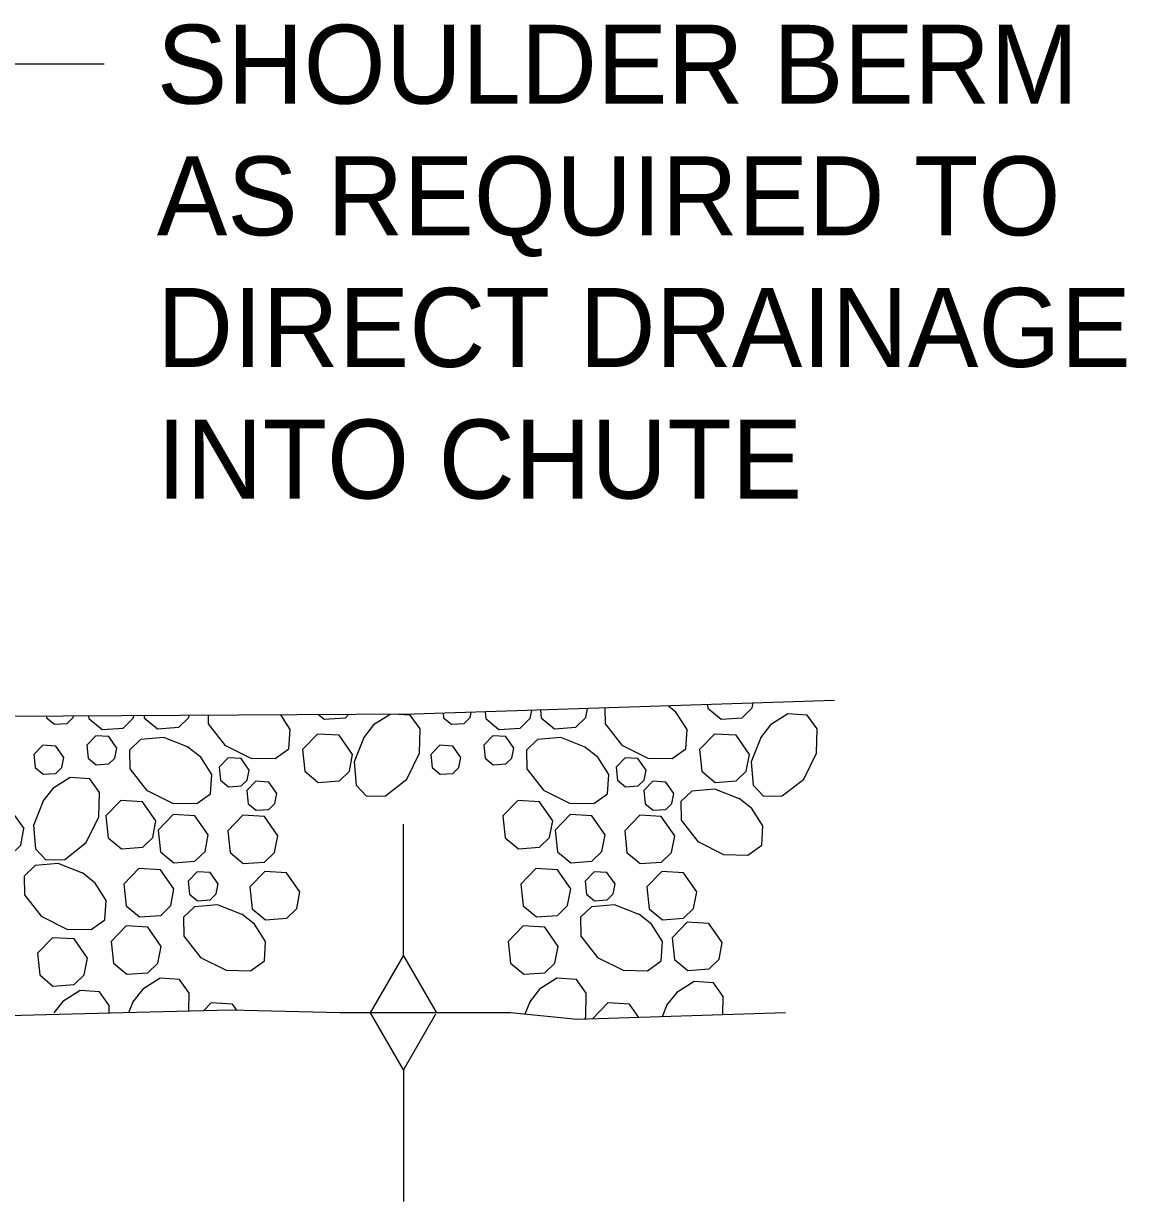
# Model space of a CAD drawing. Extents: x 49991.4 to 50021, y 49987.6 to 50011.4.
# Drawn here: x 50002.143 to 50002.981, y 49997.063 to 49997.958 of the extents above; entities that cross this region are included whole.
import ezdxf

# ---------------------------------------------------------------- set-up
doc = ezdxf.new("R2010")
doc.units = 0
for name, color, linetype in [('Level 1', 7, 'Continuous'), ('Level 2', 7, 'Continuous'), ('Level 3', 7, 'Continuous')]:
    doc.layers.add(name, color=color, linetype=linetype)

msp = doc.modelspace()

# ---------------------------------------------------------------- linework, layer by layer
at = {"layer": 'Level 1'}
for p, q in [((50002.43185, 49997.24911), (50002.43185, 49997.34911)), ((50002.40685, 49997.20581), (50002.43185, 49997.24911)), ((50002.43185, 49997.24911), (50002.45685, 49997.20581)), ((50002.22653, 49997.21479), (50002.22302, 49997.20592)), ((50002.52809, 49997.21479), (50002.5241, 49997.20473)), ((50002.63222, 49997.21231), (50002.62848, 49997.20287)), ((50002.43185, 49997.16251), (50002.40685, 49997.20581)), ((50002.45624, 49997.20474), (50002.43185, 49997.16251)), ((50002.43185, 49997.16251), (50002.43185, 49997.06251))]:
    msp.add_line(p, q, dxfattribs=at)
for points in [[(50002.75933, 49997.44303), (50002.43997, 49997.43269), (50002.12884, 49997.43102), (50001.8863, 49997.40425), (50001.69774, 49997.30927), (50001.63255, 49997.20581)], [(50002.46192, 49997.4334), (50002.46225, 49997.43009), (50002.46831, 49997.42505), (50002.478, 49997.42575), (50002.48257, 49997.43017), (50002.48333, 49997.43409)], [(50002.49384, 49997.43443), (50002.49433, 49997.42947), (50002.50444, 49997.42106), (50002.52059, 49997.42224), (50002.52819, 49997.42961), (50002.52935, 49997.43558)], [(50002.53592, 49997.4358), (50002.53649, 49997.43009), (50002.54659, 49997.42169), (50002.56274, 49997.42285), (50002.57033, 49997.43022), (50002.57165, 49997.43695)], [(50002.58486, 49997.43738), (50002.58509, 49997.42539), (50002.59779, 49997.40916), (50002.61742, 49997.39935), (50002.63591, 49997.39902), (50002.64633, 49997.40642), (50002.64731, 49997.42116), (50002.63886, 49997.43433), (50002.63308, 49997.43894)], [(50002.66276, 49997.4399), (50002.66302, 49997.43731), (50002.67312, 49997.4289), (50002.68927, 49997.43008), (50002.69687, 49997.43745), (50002.69757, 49997.44103)], [(50002.16059, 49997.43119), (50002.1607, 49997.43009), (50002.16676, 49997.42505), (50002.17645, 49997.42575), (50002.18101, 49997.43017), (50002.18123, 49997.4313)], [(50002.19259, 49997.43136), (50002.19278, 49997.42947), (50002.20289, 49997.42106), (50002.21904, 49997.42224), (50002.22663, 49997.42961), (50002.22701, 49997.43155)], [(50002.23478, 49997.43159), (50002.23493, 49997.43009), (50002.24504, 49997.42169), (50002.26118, 49997.42285), (50002.26878, 49997.43022), (50002.26908, 49997.43177)], [(50002.28341, 49997.43185), (50002.28353, 49997.42539), (50002.29623, 49997.40916), (50002.31586, 49997.39935), (50002.33436, 49997.39902), (50002.34477, 49997.40642), (50002.34576, 49997.42116), (50002.33871, 49997.43215)], [(50002.36748, 49997.4323), (50002.37157, 49997.4289), (50002.38772, 49997.43008), (50002.39014, 49997.43242)], [(50002.40195, 49997.41565), (50002.39434, 49997.39649), (50002.39587, 49997.37888), (50002.40382, 49997.37051), (50002.41811, 49997.37078), (50002.43435, 49997.38348), (50002.44415, 49997.4031), (50002.44448, 49997.4216), (50002.43708, 49997.43201), (50002.42797, 49997.43263)], [(50002.4217, 49997.43259), (50002.40917, 49997.42455), (50002.40145, 49997.41488)], [(50002.7035, 49997.41565), (50002.6959, 49997.39649), (50002.69742, 49997.37888), (50002.70538, 49997.37051), (50002.71966, 49997.37078), (50002.7359, 49997.38348), (50002.74571, 49997.4031), (50002.74604, 49997.4216), (50002.73864, 49997.43201), (50002.7239, 49997.433), (50002.71072, 49997.42455), (50002.70301, 49997.41488)], [(50002.21421, 49997.40702), (50002.20806, 49997.41577), (50002.19824, 49997.41633), (50002.19142, 49997.40925), (50002.1924, 49997.39934), (50002.19847, 49997.39429), (50002.20816, 49997.395), (50002.21272, 49997.39942), (50002.2142, 49997.40702)], [(50002.39324, 49997.40217), (50002.38299, 49997.41674), (50002.36663, 49997.41767), (50002.35526, 49997.40588), (50002.3569, 49997.38936), (50002.36701, 49997.38096), (50002.38316, 49997.38213), (50002.39076, 49997.38949), (50002.39323, 49997.40217)], [(50002.51576, 49997.40702), (50002.50961, 49997.41577), (50002.4998, 49997.41633), (50002.49298, 49997.40925), (50002.49396, 49997.39934), (50002.50002, 49997.39429), (50002.50972, 49997.395), (50002.51427, 49997.39942), (50002.51575, 49997.40702)], [(50002.69479, 49997.40217), (50002.68454, 49997.41674), (50002.66818, 49997.41767), (50002.65681, 49997.40588), (50002.65846, 49997.38936), (50002.66856, 49997.38096), (50002.68472, 49997.38213), (50002.69231, 49997.38949), (50002.69478, 49997.40217)], [(50002.17385, 49997.39982), (50002.1677, 49997.40856), (50002.15789, 49997.40912), (50002.15106, 49997.40204), (50002.15205, 49997.39214), (50002.15811, 49997.38709), (50002.1678, 49997.38779), (50002.17236, 49997.39221), (50002.17384, 49997.39981)], [(50002.26895, 49997.40732), (50002.24978, 49997.41492), (50002.23217, 49997.4134), (50002.2238, 49997.40544), (50002.22407, 49997.39116), (50002.23677, 49997.37492), (50002.2564, 49997.36511), (50002.27489, 49997.36478), (50002.28531, 49997.37218), (50002.28629, 49997.38692), (50002.27785, 49997.40009), (50002.26817, 49997.40781)], [(50002.4754, 49997.39982), (50002.46925, 49997.40856), (50002.45944, 49997.40912), (50002.45261, 49997.40204), (50002.4536, 49997.39214), (50002.45966, 49997.38709), (50002.46935, 49997.38779), (50002.47392, 49997.39221), (50002.4754, 49997.39981)], [(50002.5705, 49997.40732), (50002.55133, 49997.41492), (50002.53373, 49997.4134), (50002.52535, 49997.40544), (50002.52562, 49997.39116), (50002.53832, 49997.37492), (50002.55795, 49997.36511), (50002.57644, 49997.36478), (50002.58686, 49997.37218), (50002.58784, 49997.38692), (50002.5794, 49997.40009), (50002.56972, 49997.40781)], [(50002.31461, 49997.39021), (50002.30846, 49997.39896), (50002.29865, 49997.39951), (50002.29183, 49997.39244), (50002.29281, 49997.38253), (50002.29888, 49997.37748), (50002.30857, 49997.37819), (50002.31313, 49997.38261), (50002.31461, 49997.39021)], [(50002.61617, 49997.39021), (50002.61002, 49997.39896), (50002.6002, 49997.39951), (50002.59338, 49997.39244), (50002.59437, 49997.38253), (50002.60043, 49997.37748), (50002.61013, 49997.37819), (50002.61468, 49997.38261), (50002.61616, 49997.39021)], [(50002.15837, 49997.3673), (50002.15076, 49997.34814), (50002.15229, 49997.33053), (50002.16024, 49997.32216), (50002.17453, 49997.32243), (50002.19077, 49997.33513), (50002.20057, 49997.35476), (50002.2009, 49997.37326), (50002.1935, 49997.38367), (50002.17876, 49997.38466), (50002.16559, 49997.37621), (50002.15787, 49997.36654)], [(50002.33575, 49997.37243), (50002.3296, 49997.38118), (50002.31979, 49997.38174), (50002.31297, 49997.37467), (50002.31395, 49997.36475), (50002.32002, 49997.35971), (50002.32971, 49997.36041), (50002.33427, 49997.36483), (50002.33574, 49997.37243)], [(50002.63731, 49997.37243), (50002.63116, 49997.38118), (50002.62134, 49997.38174), (50002.61452, 49997.37467), (50002.6155, 49997.36475), (50002.62157, 49997.35971), (50002.63126, 49997.36041), (50002.63582, 49997.36483), (50002.6373, 49997.37243)], [(50002.68763, 49997.36828), (50002.66846, 49997.37588), (50002.65085, 49997.37435), (50002.64249, 49997.3664), (50002.64275, 49997.35211), (50002.65546, 49997.33588), (50002.67508, 49997.32607), (50002.69358, 49997.32574), (50002.70399, 49997.33314), (50002.70498, 49997.34787), (50002.69653, 49997.36105), (50002.68685, 49997.36877)], [(50002.24384, 49997.35169), (50002.2336, 49997.36627), (50002.21724, 49997.36721), (50002.20586, 49997.35541), (50002.20751, 49997.33889), (50002.21762, 49997.33048), (50002.23377, 49997.33166), (50002.24136, 49997.33903), (50002.24383, 49997.35169)], [(50002.54539, 49997.35169), (50002.53515, 49997.36627), (50002.51879, 49997.36721), (50002.50742, 49997.35541), (50002.50906, 49997.33889), (50002.51917, 49997.33048), (50002.53532, 49997.33166), (50002.54292, 49997.33903), (50002.54539, 49997.35169)], [(50002.14361, 49997.34581), (50002.13336, 49997.36039), (50002.117, 49997.36132), (50002.10563, 49997.34953), (50002.10727, 49997.33301), (50002.11738, 49997.3246), (50002.13353, 49997.32577), (50002.14113, 49997.33314), (50002.14359, 49997.34581)], [(50002.28358, 49997.34101), (50002.27333, 49997.35558), (50002.25697, 49997.35651), (50002.2456, 49997.34473), (50002.24725, 49997.3282), (50002.25735, 49997.31979), (50002.2735, 49997.32097), (50002.2811, 49997.32834), (50002.28356, 49997.341)], [(50002.33644, 49997.34041), (50002.32619, 49997.35498), (50002.30983, 49997.35591), (50002.29846, 49997.34412), (50002.30011, 49997.3276), (50002.31021, 49997.31919), (50002.32636, 49997.32037), (50002.33396, 49997.32773), (50002.33642, 49997.3404)], [(50002.58513, 49997.34101), (50002.57488, 49997.35558), (50002.55852, 49997.35651), (50002.54715, 49997.34473), (50002.5488, 49997.3282), (50002.5589, 49997.31979), (50002.57506, 49997.32097), (50002.58266, 49997.32834), (50002.58512, 49997.341)], [(50002.63799, 49997.34041), (50002.62774, 49997.35498), (50002.61138, 49997.35591), (50002.60001, 49997.34412), (50002.60166, 49997.3276), (50002.61176, 49997.31919), (50002.62792, 49997.32037), (50002.63552, 49997.32773), (50002.63798, 49997.3404)], [(50002.18875, 49997.31159), (50002.16957, 49997.31919), (50002.15197, 49997.31768), (50002.14361, 49997.30972), (50002.14386, 49997.29543), (50002.15657, 49997.27919), (50002.1762, 49997.26938), (50002.1947, 49997.26906), (50002.20511, 49997.27646), (50002.2061, 49997.29119), (50002.19765, 49997.30437), (50002.18797, 49997.31209)], [(50002.25749, 49997.29994), (50002.24725, 49997.31452), (50002.23089, 49997.31545), (50002.21952, 49997.30366), (50002.22117, 49997.28714), (50002.23127, 49997.27874), (50002.24742, 49997.2799), (50002.25503, 49997.28727), (50002.25749, 49997.29994)], [(50002.29108, 49997.30372), (50002.28493, 49997.31246), (50002.27511, 49997.31303), (50002.26828, 49997.30595), (50002.26927, 49997.29604), (50002.27533, 49997.291), (50002.28503, 49997.2917), (50002.28959, 49997.29612), (50002.29107, 49997.30372)], [(50002.35324, 49997.29773), (50002.34299, 49997.3123), (50002.32664, 49997.31324), (50002.31526, 49997.30144), (50002.31691, 49997.28492), (50002.32701, 49997.27652), (50002.34317, 49997.27769), (50002.35076, 49997.28506), (50002.35323, 49997.29773)], [(50002.55905, 49997.29994), (50002.54881, 49997.31452), (50002.53245, 49997.31545), (50002.52108, 49997.30366), (50002.52272, 49997.28714), (50002.53283, 49997.27874), (50002.54897, 49997.2799), (50002.55658, 49997.28727), (50002.55904, 49997.29994)], [(50002.59263, 49997.30372), (50002.58648, 49997.31246), (50002.57667, 49997.31303), (50002.56984, 49997.30595), (50002.57083, 49997.29604), (50002.57689, 49997.291), (50002.58659, 49997.2917), (50002.59114, 49997.29612), (50002.59262, 49997.30372)], [(50002.65479, 49997.29773), (50002.64454, 49997.3123), (50002.62819, 49997.31324), (50002.61682, 49997.30144), (50002.61846, 49997.28492), (50002.62857, 49997.27652), (50002.64472, 49997.27769), (50002.65232, 49997.28506), (50002.65479, 49997.29773)], [(50002.30981, 49997.28037), (50002.29065, 49997.28796), (50002.27304, 49997.28644), (50002.26467, 49997.27849), (50002.26494, 49997.2642), (50002.27764, 49997.24797), (50002.29727, 49997.23815), (50002.31576, 49997.23783), (50002.32618, 49997.24522), (50002.32716, 49997.25996), (50002.31871, 49997.27314), (50002.30904, 49997.28086)], [(50002.61137, 49997.28037), (50002.5922, 49997.28796), (50002.57459, 49997.28644), (50002.56623, 49997.27849), (50002.56649, 49997.2642), (50002.5792, 49997.24797), (50002.59882, 49997.23815), (50002.61732, 49997.23783), (50002.62774, 49997.24522), (50002.62872, 49997.25996), (50002.62027, 49997.27314), (50002.61059, 49997.28086)], [(50002.67407, 49997.25917), (50002.66382, 49997.27375), (50002.64747, 49997.27468), (50002.63609, 49997.26289), (50002.63774, 49997.24637), (50002.64784, 49997.23796), (50002.664, 49997.23914), (50002.6716, 49997.2465), (50002.67406, 49997.25917)], [(50002.24786, 49997.25631), (50002.23761, 49997.27089), (50002.22125, 49997.27182), (50002.20988, 49997.26003), (50002.21153, 49997.24351), (50002.22163, 49997.23511), (50002.23778, 49997.23627), (50002.24538, 49997.24364), (50002.24785, 49997.25631)], [(50002.54941, 49997.25631), (50002.53917, 49997.27089), (50002.52281, 49997.27182), (50002.51144, 49997.26003), (50002.51308, 49997.24351), (50002.52319, 49997.23511), (50002.53934, 49997.23627), (50002.54693, 49997.24364), (50002.5494, 49997.25631)], [(50002.19184, 49997.24739), (50002.1816, 49997.26196), (50002.16524, 49997.2629), (50002.15387, 49997.25111), (50002.15552, 49997.23459), (50002.16562, 49997.22617), (50002.18177, 49997.22735), (50002.18936, 49997.23472), (50002.19183, 49997.24738)], [(50002.26884, 49997.20711), (50002.26908, 49997.22074), (50002.26168, 49997.23116), (50002.24694, 49997.23214), (50002.23377, 49997.2237), (50002.22605, 49997.21402)], [(50002.56969, 49997.20102), (50002.5703, 49997.20225), (50002.57063, 49997.22074), (50002.56323, 49997.23116), (50002.54849, 49997.23214), (50002.53532, 49997.2237), (50002.5276, 49997.21402)], [(50002.67451, 49997.20432), (50002.67476, 49997.21826), (50002.66736, 49997.22867), (50002.65262, 49997.22966), (50002.63945, 49997.22121), (50002.63173, 49997.21154)], [(50002.20823, 49997.20581), (50002.20833, 49997.21144), (50002.20093, 49997.22186), (50002.1862, 49997.22284), (50002.17302, 49997.2144), (50002.16617, 49997.20581)], [(50002.30524, 49997.20781), (50002.30202, 49997.21239), (50002.28566, 49997.21332), (50002.27994, 49997.2074)], [(50002.61065, 49997.20231), (50002.60357, 49997.21239), (50002.58721, 49997.21332), (50002.57584, 49997.20153), (50002.57587, 49997.20122)], [(50002.72205, 49997.20581), (50002.56386, 49997.20084), (50002.51306, 49997.20581), (50002.38389, 49997.20581), (50002.30039, 49997.20793), (50002.21885, 49997.20581), (50001.9955, 49997.20001), (50001.80169, 49997.20581)]]:
    msp.add_lwpolyline(points, dxfattribs=at)
at = {"layer": 'Level 3'}
msp.add_lwpolyline([(50002.20452, 49997.92661), (50002.02377, 49997.92661), (50001.8863, 49997.40425)], dxfattribs=at)

# ---------------------------------------------------------------- texts
at = {"layer": 'Level 2'}
for s, p in [('SHOULDER BERM', (50002.24452, 49997.89661)), ('AS REQUIRED TO', (50002.24452, 49997.79661)), ('DIRECT DRAINAGE', (50002.24452, 49997.69661)), ('INTO CHUTE', (50002.24452, 49997.59661))]:
    msp.add_text(s, height=0.06, dxfattribs=at).set_placement(p)

doc.saveas('drawing.dxf')
